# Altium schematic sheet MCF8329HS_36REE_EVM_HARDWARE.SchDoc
size 431 x 279 mm; Date: Not shown in title block; ApprovedBy: Not shown in title block; CheckedBy: Not shown in title block; Author: Not shown in title block; CompanyName: Not shown in title block; Engineer: Not shown in title block; Organization: Not shown in title block; Address1: Not shown in title block; Address2: Not shown in title block; Address3: Not shown in title block; Address4: Not shown in title block; DocumentNumber: 5; Revision: Use project parameter SCH_Rev; SheetNumber: 5; SheetTotal: 5; PageSetup: Record=PageOptions¦CenterHorizontal=True¦CenterVertical=True¦PrintScale=1.00¦XCorrection=1.00¦YCorrection=1.00¦PrintKind=0¦BorderSize=5000000¦LeftOffset=0¦BottomOffset=0¦Orientation=2¦PaperLength=1000¦PaperWidth=1000¦Scale=100¦PaperSource=15¦PrintQuality=600¦MediaType=1¦DitherType=10¦PaperKind=Letter¦PrintScaleMode=1
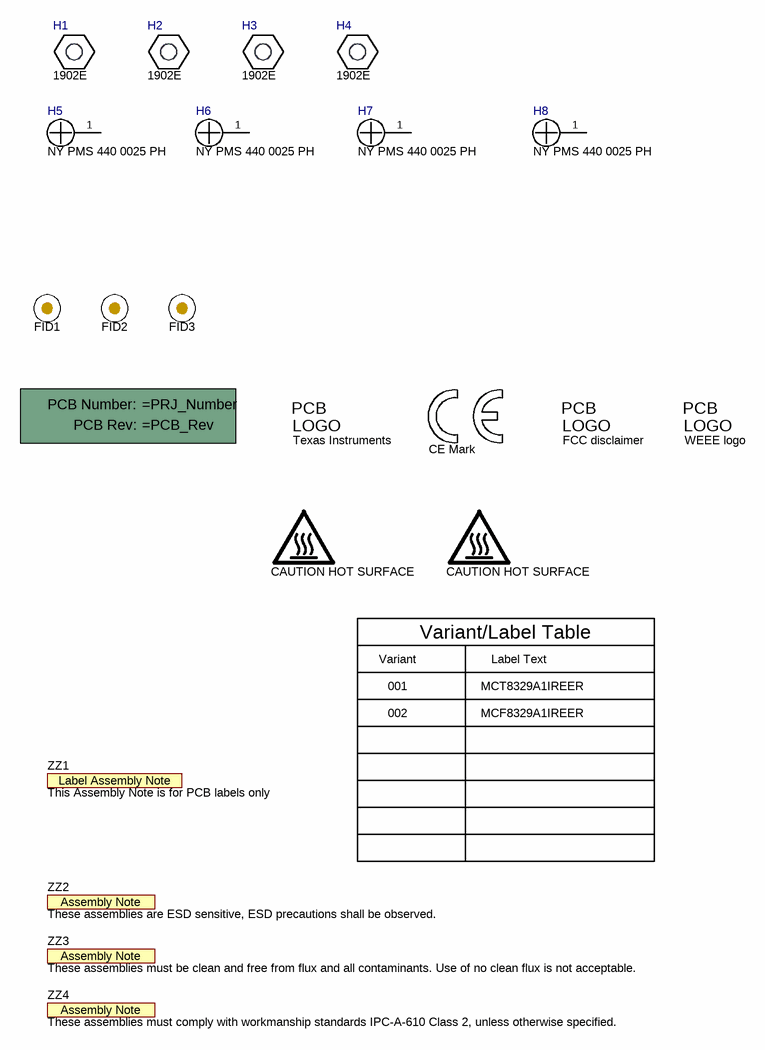
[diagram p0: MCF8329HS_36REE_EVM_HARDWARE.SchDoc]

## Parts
!PCB1  Printed Circuit Board  (value not drawn)  (mechanical)
FID1  Fiducial  [Fiducial10-20]  (value not drawn)
FID2  Fiducial  [Fiducial10-20]  (value not drawn)
FID3  Fiducial  [Fiducial10-20]  (value not drawn)
H1  1902E  [Keystone_1902E]
H2  1902E  [Keystone_1902E]
H3  1902E  [Keystone_1902E]
H4  1902E  [Keystone_1902E]
H5  NY PMS 440 0025 PH  [NY PMS 440 0025 PH]
H6  NY PMS 440 0025 PH  [NY PMS 440 0025 PH]
H7  NY PMS 440 0025 PH  [NY PMS 440 0025 PH]
H8  NY PMS 440 0025 PH  [NY PMS 440 0025 PH]
Logo1  CE Mark  [CE_Mark_5mm]  (no BOM)
Logo2  Texas Instruments  [TI_Stacked_Overlay_Small]  (no BOM)
Logo3  FCC disclaimer  [FCC_disclaimer]  (no BOM)
Logo4  WEEE logo  [WEEE_Minimum]  (no BOM)
LOGO5  CAUTION HOT SURFACE  [IEC_HotSurface_Small]  (no BOM)
LOGO6  CAUTION HOT SURFACE  [IEC_HotSurface_Small]  (no BOM)
ZZ1  This Assembly Note is for PCB labels only  [AssemblyNoteLabel]  (no BOM)
ZZ2  These assemblies are ESD sensitive, ESD precautions shall be observed.  [AssemblyNote]  (no BOM)
ZZ3  These assemblies must be clean and free from flux and all contaminants. Use of no clean flux is not acceptable.  [AssemblyNote]  (no BOM)
ZZ4  These assemblies must comply with workmanship standards IPC-A-610 Class 2, unless otherwise specified.  [AssemblyNote]  (no BOM)

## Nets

Not connected (* = marked no-connect by the designer): H5 1; H6 1; H7 1; H8 1

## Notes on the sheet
- Variant
- Variant/Label Table
- Label Text
- 001
- 002
- MCT8329A1IREER
- MCF8329A1IREER

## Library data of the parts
!PCB1 = CMP-0003618-2: Manufacturer: Any
FID1-FID3 = CMP-0077181-1: Fiducial mark.  There is nothing to buy or mount.
H1-H4 = CMP-0003611-1: Standoff, Hex, 1"L #4-40 Nylon; Manufacturer: Keystone; CompType: Hardware
H5-H8 = CMP-0003617-1: Machine Screw, Round, #4-40 x 1/4, Nylon, Philips panhead; Manufacturer: B&F Fastener Supply; CompType: Hardware
Logo1 = CMP-0074844-2: Manufacturer: Texas Instruments; SymbolCreator: a0412235; AEC Category: Q200; CompType: IC
Logo2 = CMP-0074838-1: Texas Instrument Corporate Signature; SymbolCreator: a0412235; Lib Reference: TI_Logo; Library Reference: Logo
Logo3 = CMP-0074847-1: FCC_disclaimer; Library Reference: Logo
Logo4 = CMP-0074769-4: Manufacturer: Texas Instruments; AEC Category: Q200; CompType: IC
LOGO5 LOGO6 = CMP-0074837-2: IEC 61010-1 Hot Surface Warning; Manufacturer: Texas Instruments; SymbolCreator: a0412235; AEC Category: Q200; CompType: IC
ZZ1 = CMP-0003616-3
ZZ2 = CMP-0077236-1
ZZ3 = CMP-0077237-1
ZZ4 = CMP-0077238-1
